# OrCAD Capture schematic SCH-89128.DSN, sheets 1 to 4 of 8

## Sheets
1 08 K20: size D; title: PNEV7220BP2; rev: D; company: NXP Semiconductors; note: SCH-89128 PDF: SPF-89128; note: 6501 William Cannon Drive West; note: Austin, TX 78735-8598
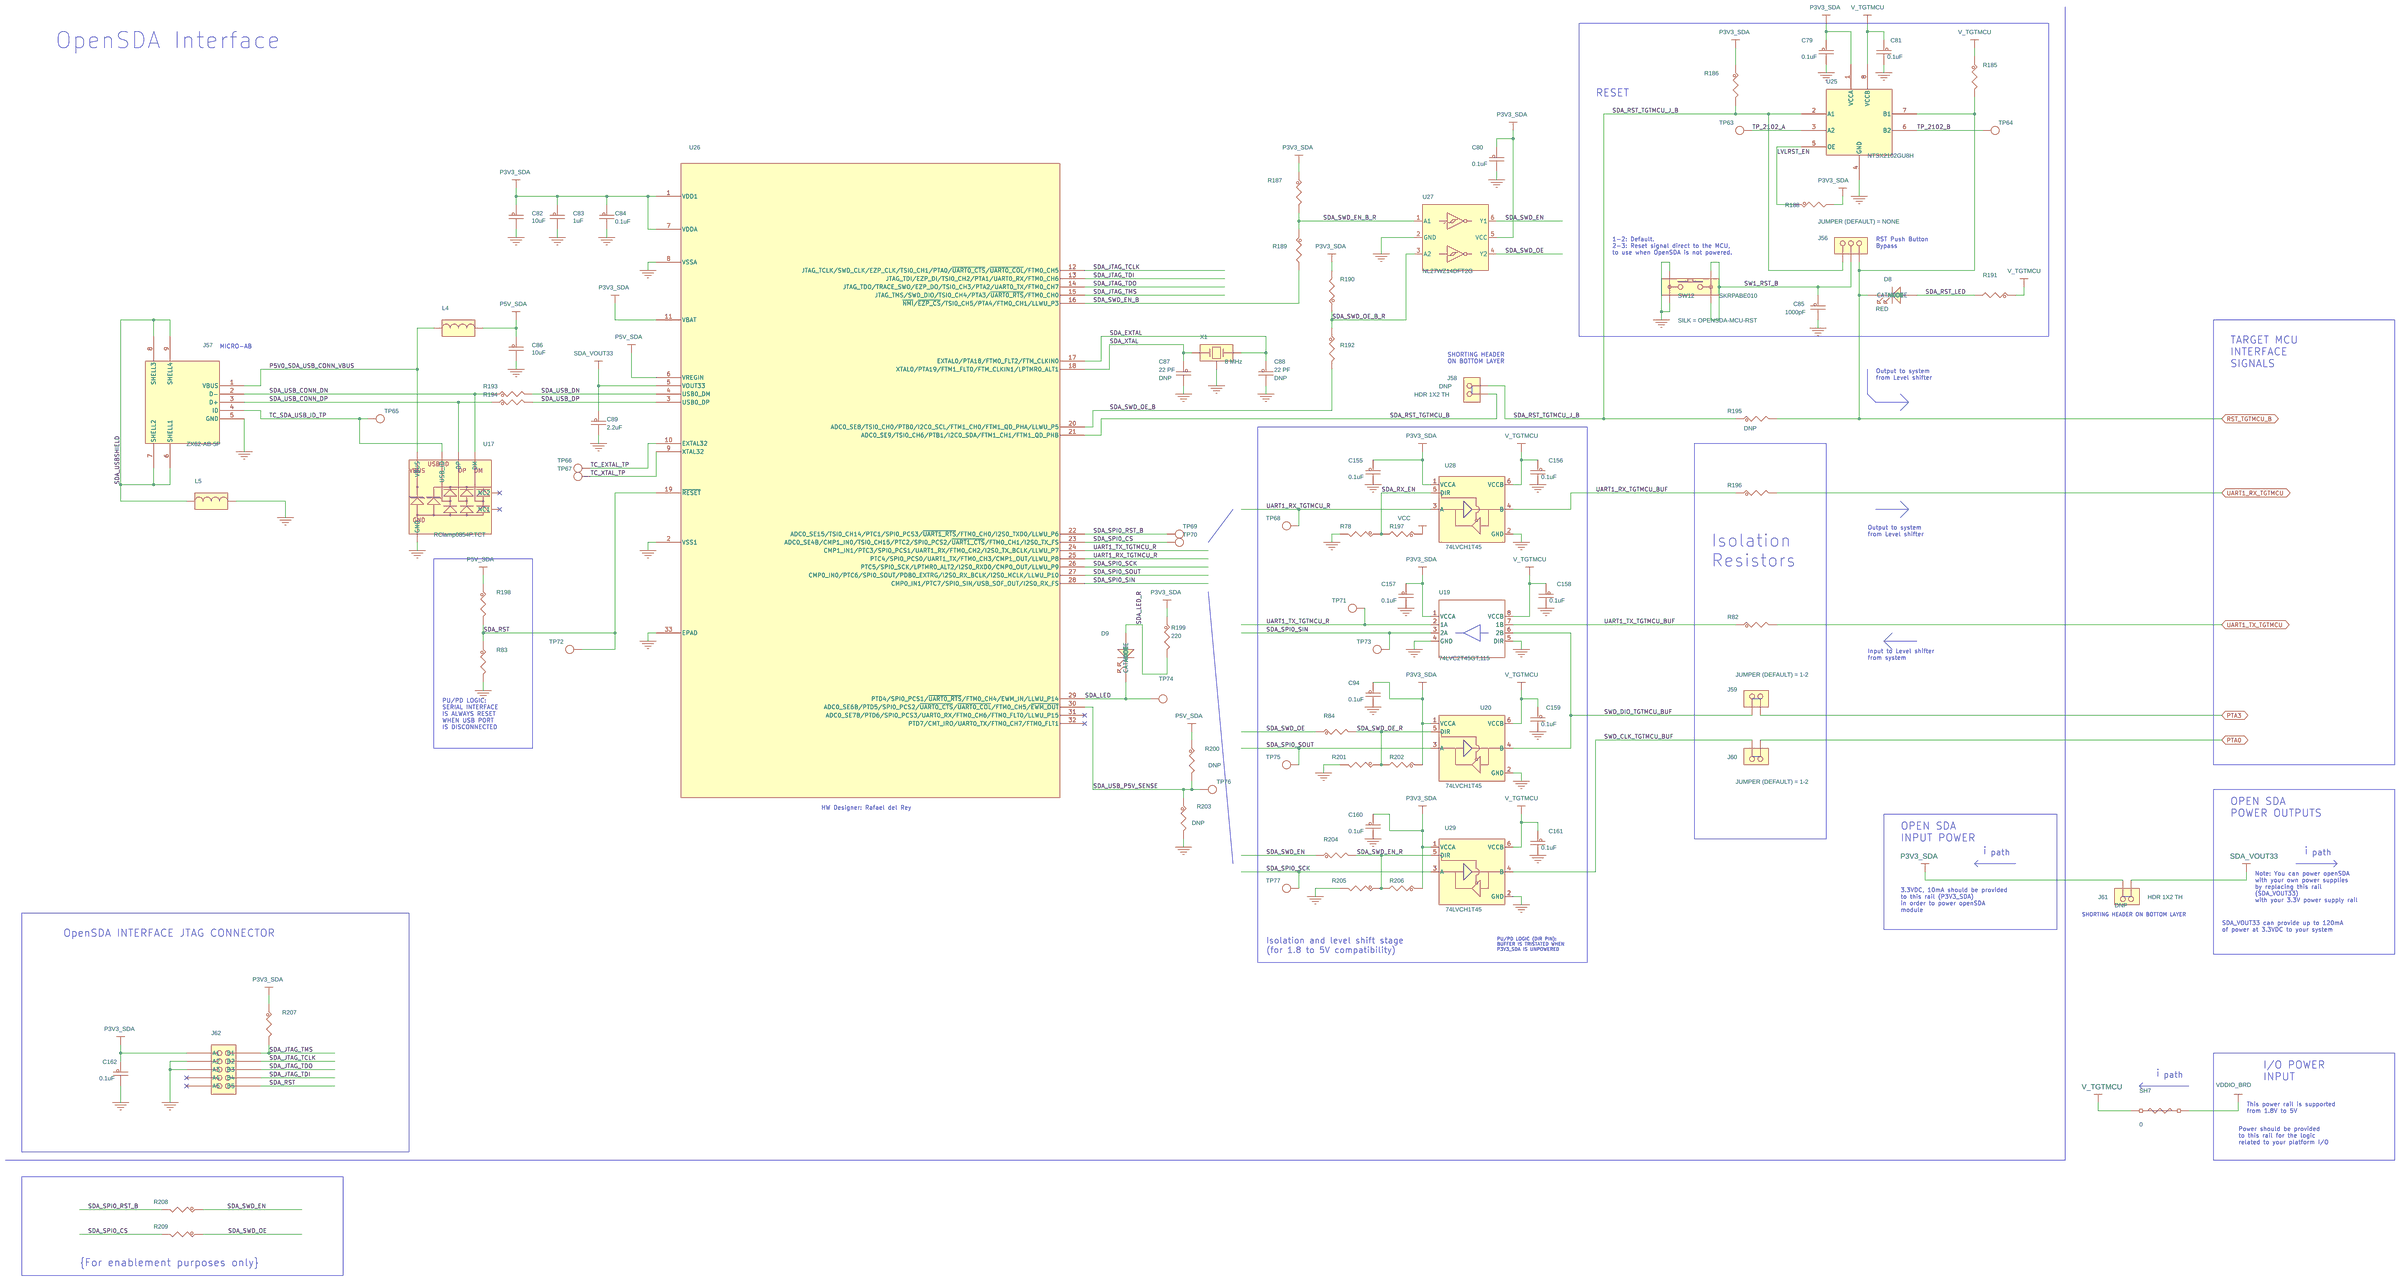
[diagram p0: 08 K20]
2 07 K82: size D
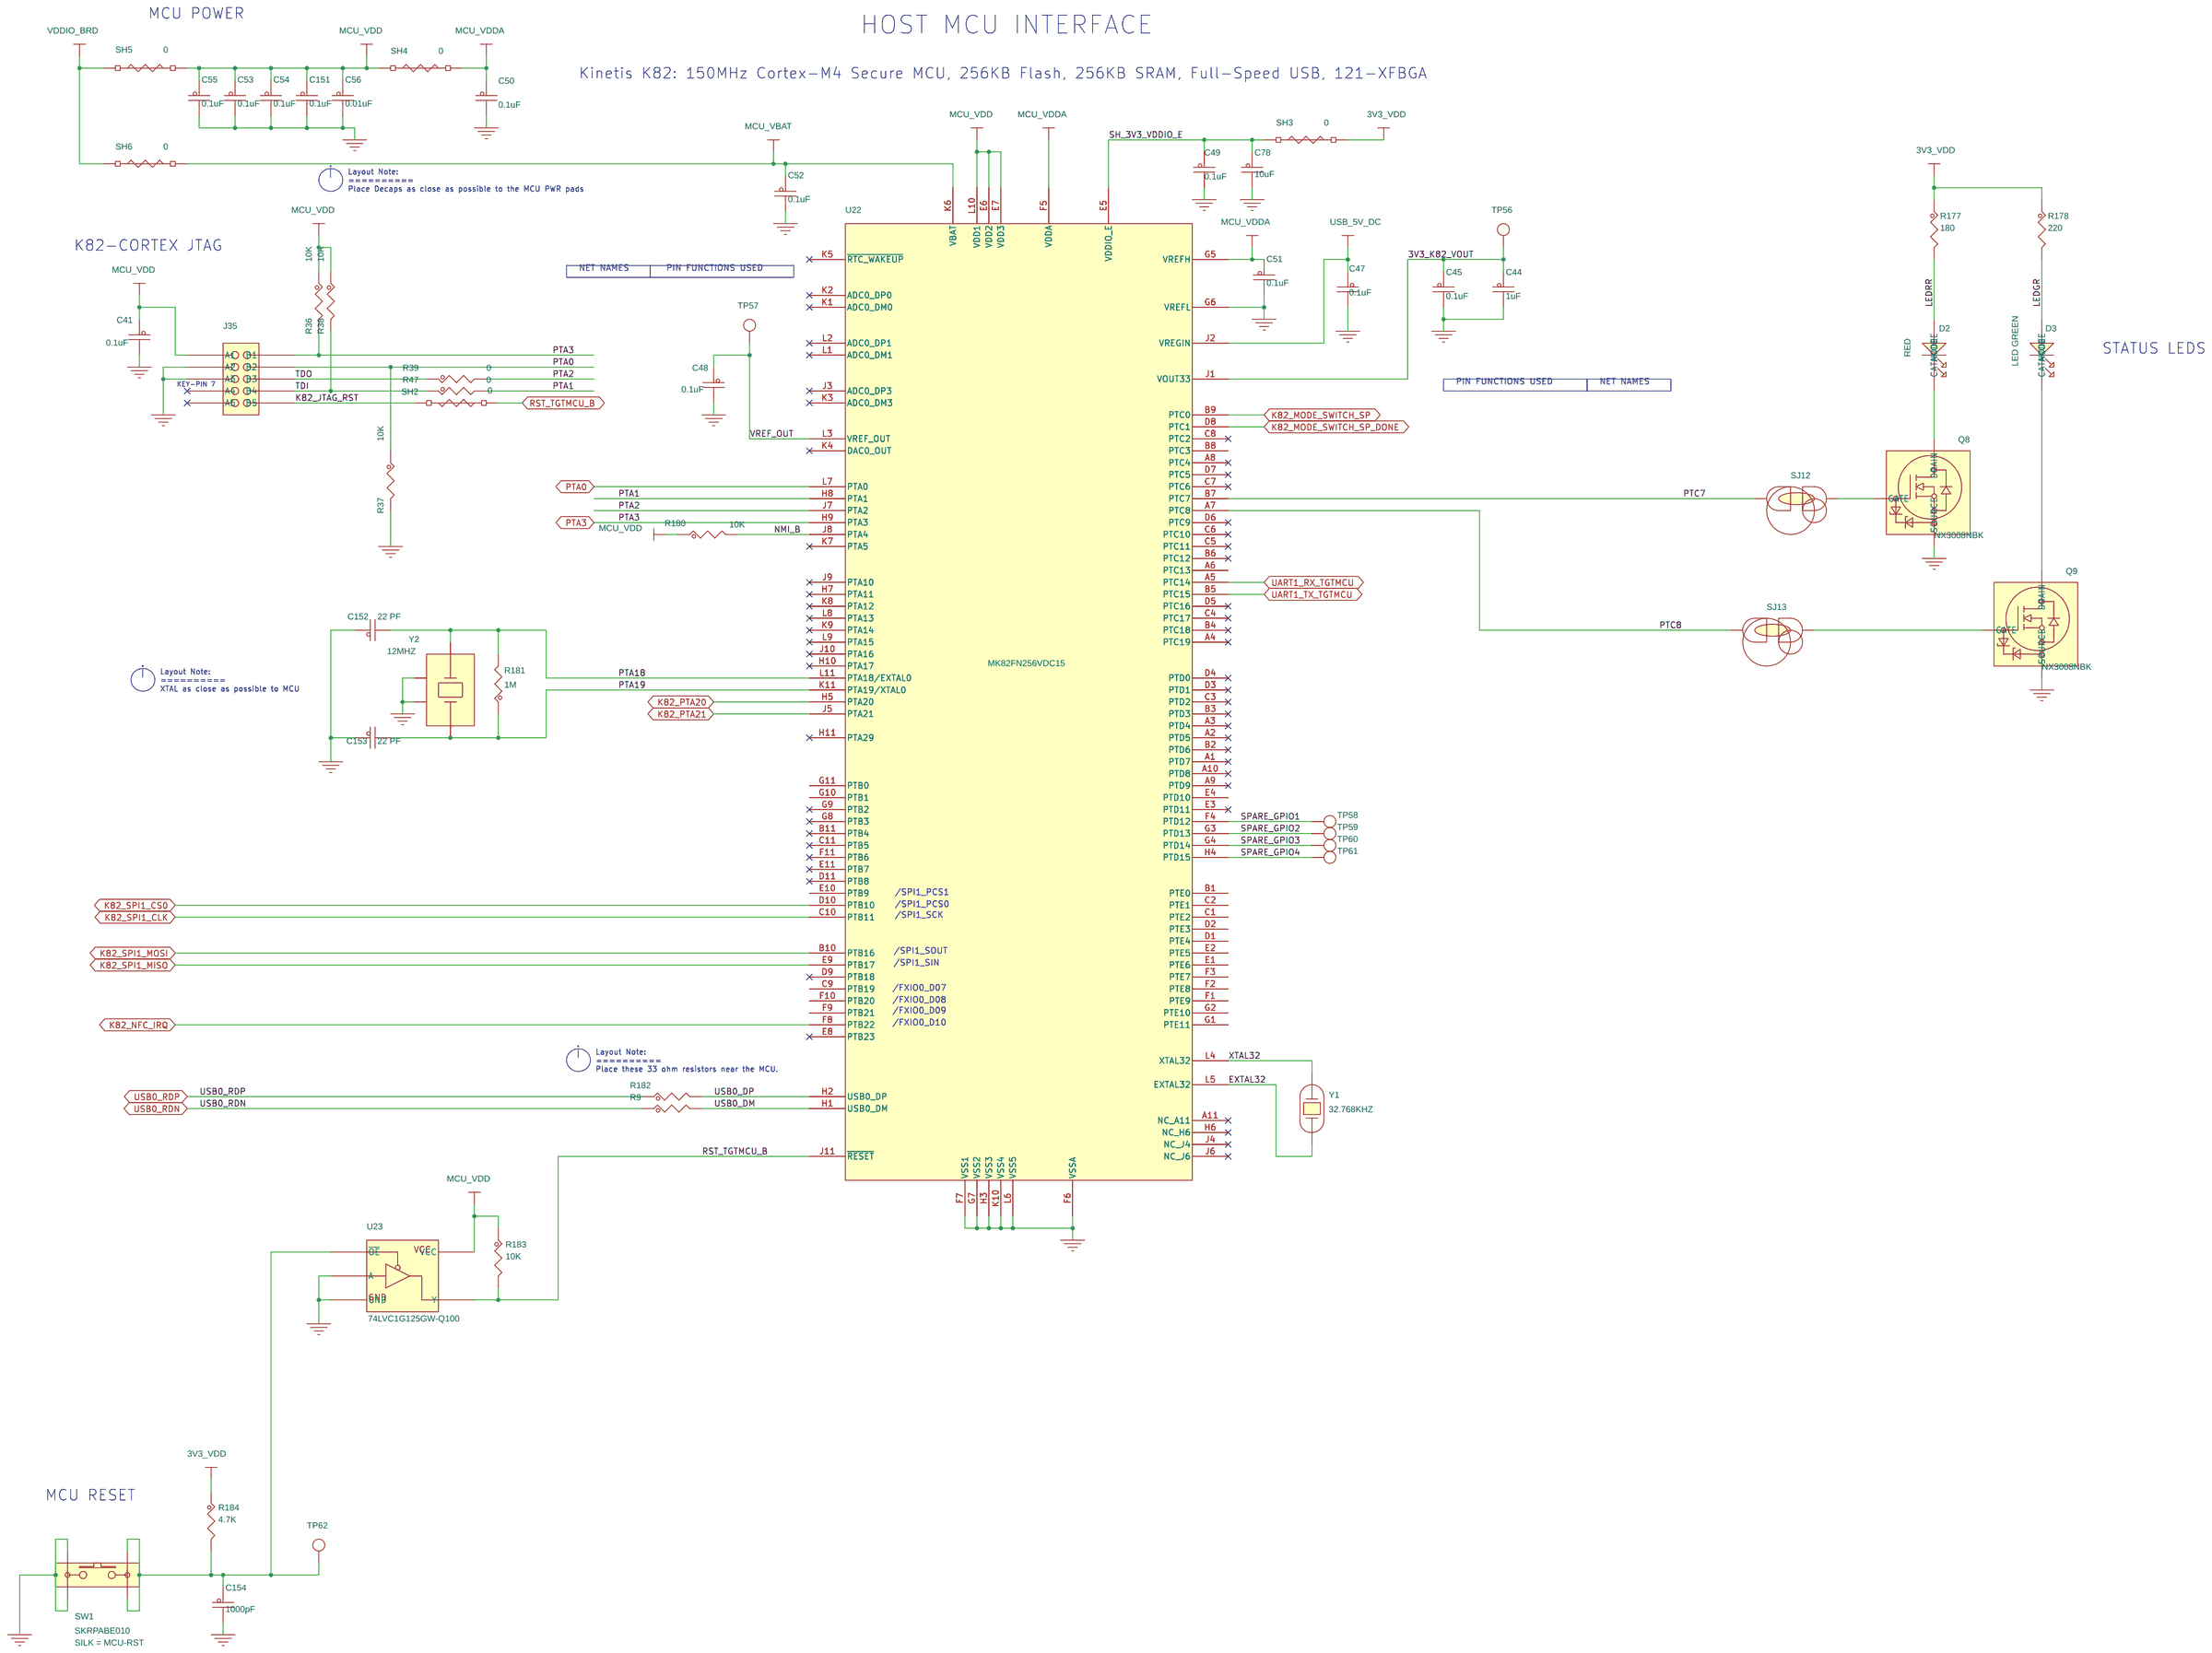
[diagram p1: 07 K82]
3 01 Title
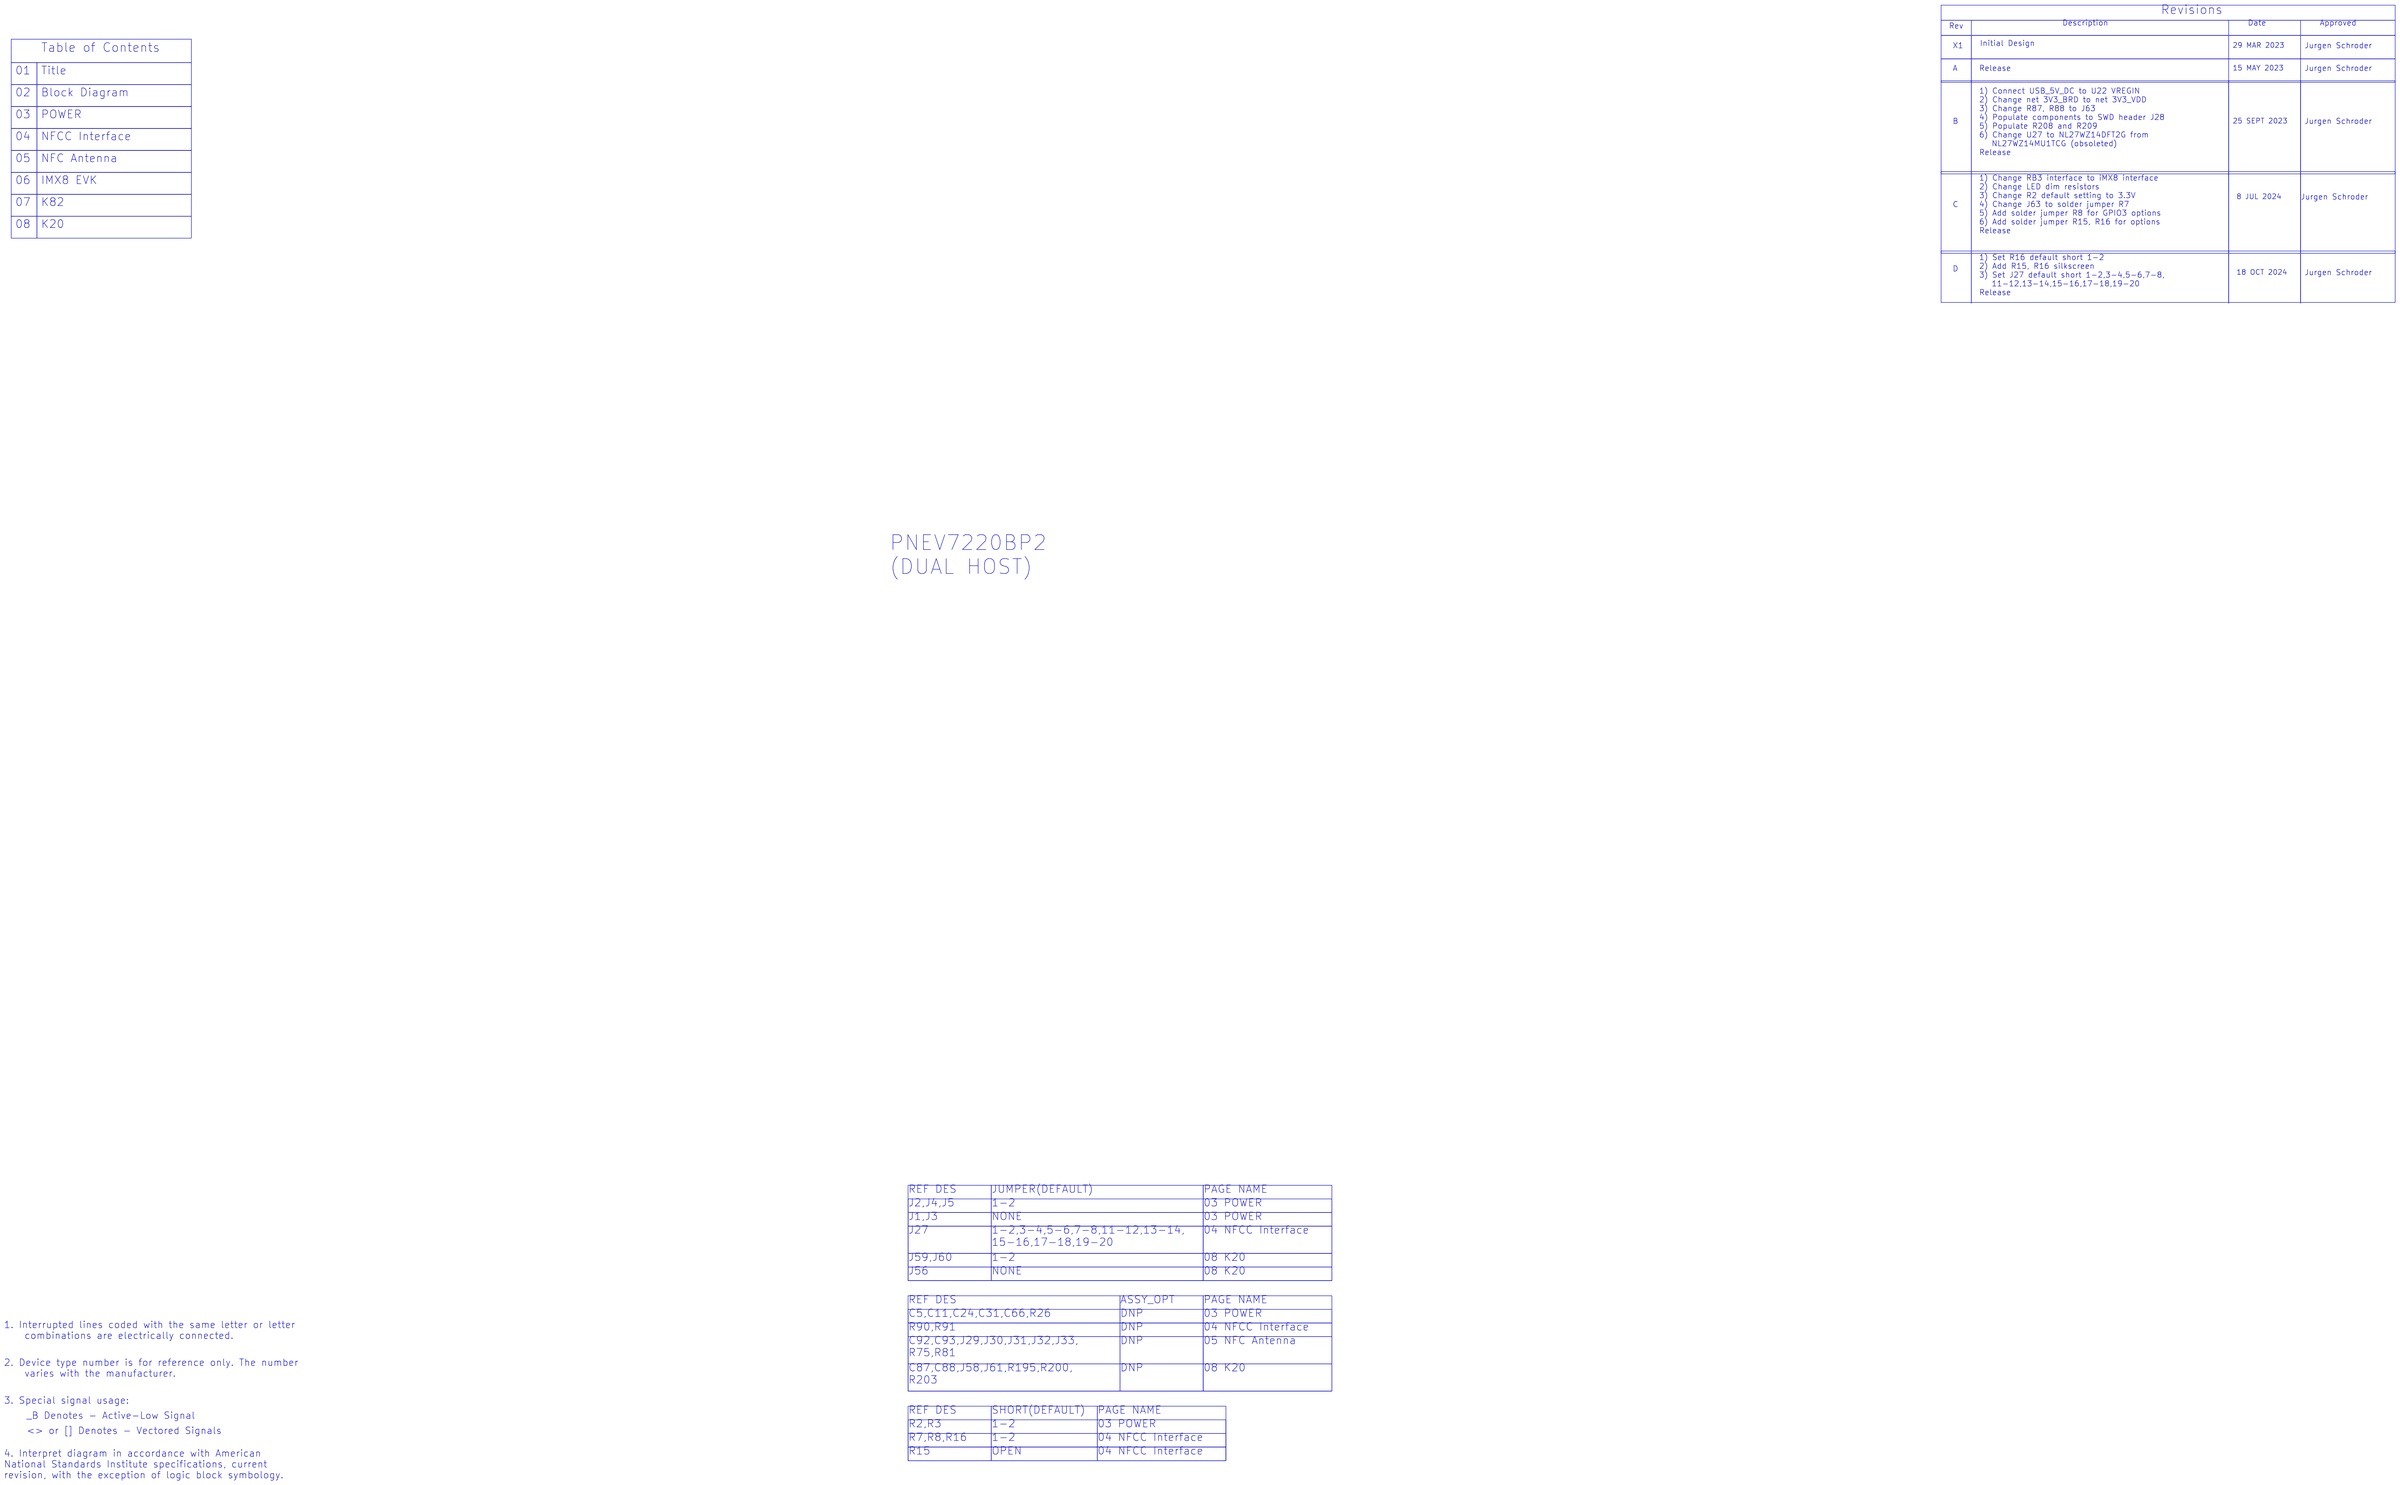
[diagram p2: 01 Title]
4 02 Block Diagram
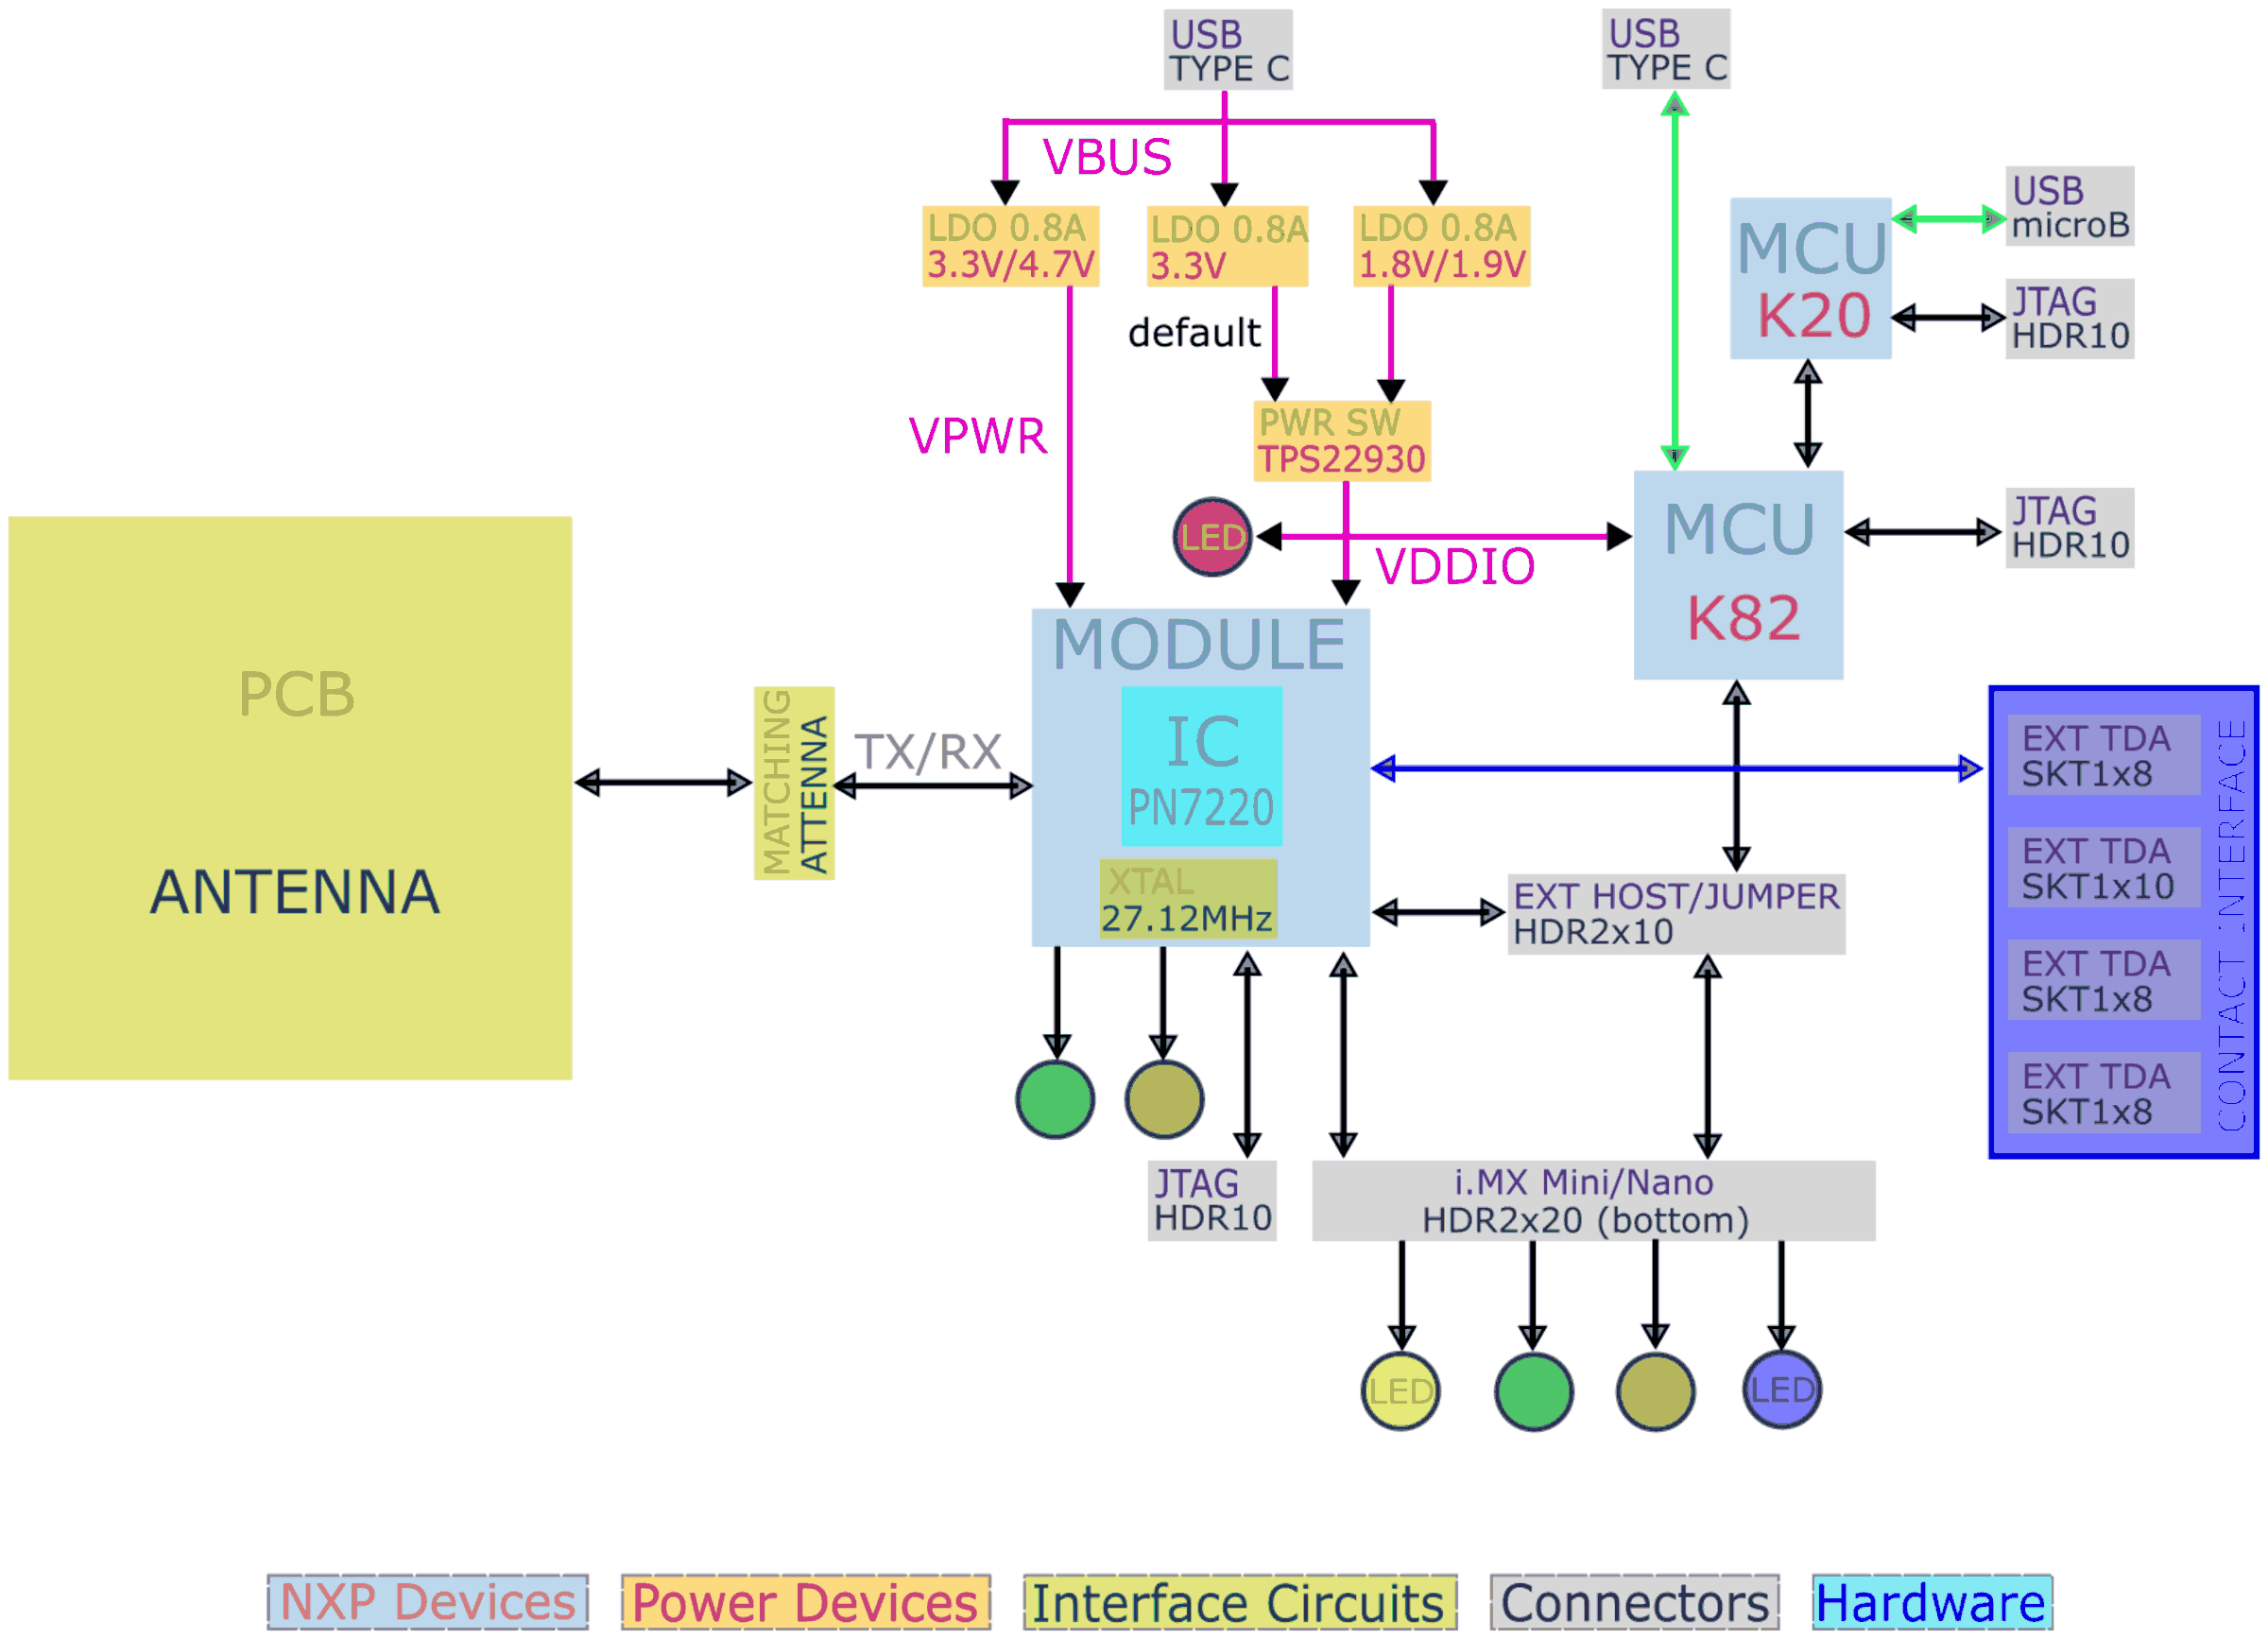
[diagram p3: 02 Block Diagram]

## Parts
sheet 07 K82
C41  0.1uF  [CC0402_25]
C44  1uF  [CC0603_OV]
C45  0.1uF  [CC0402_25]
C47  0.1uF  [CC0402_25]
C48  0.1uF  [CC0402_25]
C49  0.1uF  [CC0402_25]
C50  0.1uF  [CC0402_25]
C51  0.1uF  [CC0402_25]
C52  0.1uF  [CC0402_25]
C53  0.1uF  [CC0402_25]
C54  0.1uF  [CC0402_25]
C55  0.1uF  [CC0402_25]
C56  0.01uF  [CC0402_25]
C78  10uF  [CC0603_OV]
C151  0.1uF  [CC0402_25]
C152  22 PF  [CC0603_OV]
C153  22 PF  [CC0603_OV]
C154  1000pF  [CC0402_25]
D2  RED  [LED_0603]
D3  LED GREEN  [LED_0603]
J35  HDR 2X5  [hdr_5X2_ftsh_th_nsp]
Q8  NX3008NBK  [SOT23_A]
Q9  NX3008NBK  [SOT23_A]
R9  33  [RC0402_25]
R36  10K  [RC0402_25]
R37  10K  [RC0402_25]
R38  10K  [RC0402_25]
R39  0  [RC0603_OV]
R47  0  [RC0603_OV]
R177  180  [RC0402_25]
R178  220  [RC0402_25]
R180  10K  [RC0402_25]
R181  1M  [RC0402_25]
R182  33  [RC0402_25]
R183  10K  [RC0402_25]
R184  4.7K  [RC0402_25]
SH2  0  [SH0603]
SH3  0  [SH0603]
SH4  0  [SH0603]
SH5  0  [SH0603]
SH6  0  [SH0603]
SJ12  0402 JUMPER  [0402_solder_blob_jumper_short]
SJ13  0402 JUMPER  [0402_solder_blob_jumper_short]
SW1  SKRPABE010  [sw4_skrp]
TP56  TPAD_040  [TPAD_040]
TP57  TPAD_040  [TPAD_040]
TP58  TPAD_040  [TPAD_040]
TP59  TPAD_040  [TPAD_040]
TP60  TPAD_040  [TPAD_040]
TP61  TPAD_040  [TPAD_040]
TP62  TPAD_040  [TPAD_040]
U22  MK82FN256VDC15  [BGA121_0P65_8X8MM]
U23  74LVC1G125GW-Q100  [sc70-5]
Y1  32.768KHZ  [XTAL2-3P2X1P5-SM]
Y2  12MHZ  [xtal4_3p3x2p6_sm_fl]
sheet 08 K20
C79  0.1uF  [CC0402_25]
C80  0.1uF  [CC0402_25]
C81  0.1uF  [CC0402_25]
C82  10uF  [CC0603_OV]
C83  1uF  [CC0603_OV]
C84  0.1uF  [CC0402_25]
C85  1000pF  [CC0402_25]
C86  10uF  [CC0603_OV]
C87  22 PF  [CC0603_OV]
C88  22 PF  [CC0603_OV]
C89  2.2uF  [CC0603_OV]
C94  0.1uF  [CC0402_25]
C155  0.1uF  [CC0402_25]
C156  0.1uF  [CC0402_25]
C157  0.1uF  [CC0402_25]
C158  0.1uF  [CC0402_25]
C159  0.1uF  [CC0402_25]
C160  0.1uF  [CC0402_25]
C161  0.1uF  [CC0402_25]
C162  0.1uF  [CC0402_25]
D8  RED  [LED_0603]
D9  LED GREEN  [LED_0603]
J56  HDR TH 1X3  [HDR103]
J57  ZX62-AB-5P  [MICRO_USB_CONN_9PIN]
J58  HDR 1X2 TH  [SH_HDR102_BOTTOM]
J59  HDR 1X2 TH  [HDR_1X2]
J60  HDR 1X2 TH  [HDR_1X2]
J61  HDR 1X2 TH  [SH_HDR102_BOTTOM]
J62  HDR 2X5  [hdr_5X2_ftsh_th_nsp]
L4  330 OHM  [IND_0805]
L5  330 OHM  [IND_0805]
R78  10K  [RC0402_25]
R82  1.0K  [RC0402_25]
R83  10K  [RC0402_25]
R84  0  [RC0603_OV]
R185  180K  [RC0805_OV]
R186  10K  [RC0402_25]
R187  10K  [RC0402_25]
R188  4.7K  [RC0402_25]
R189  0  [RC0603_OV]
R190  10K  [RC0402_25]
R191  100  [RC0402_25]
R192  0  [RC0603_OV]
R193  33  [RC0402_25]
R194  33  [RC0402_25]
R195  0  [RC0603_OV]
R196  1.0K  [RC0402_25]
R197  4.7K  [RC0402_25]
R198  4.7K  [RC0402_25]
R199  220  [RC0402_25]
R200  4.7K  [RC0402_25]
R201  10K  [RC0402_25]
R202  4.7K  [RC0402_25]
R203  10K  [RC0402_25]
R204  0  [RC0603_OV]
R205  10K  [RC0402_25]
R206  4.7K  [RC0402_25]
R207  10K  [RC0402_25]
R208  0  [RC0603_OV]
R209  0  [RC0603_OV]
SH7  0  [SH0603]
SW12  SKRPABE010  [sw4_skrp]
TP63  TPAD_030  [TPAD_030]
TP64  TPAD_030  [TPAD_030]
TP65  TPAD_030  [TPAD_030]
TP66  TPAD_030  [TPAD_030]
TP67  TPAD_030  [TPAD_030]
TP68  TPAD_030  [TPAD_030]
TP69  TPAD_030  [TPAD_030]
TP70  TPAD_030  [TPAD_030]
TP71  TPAD_030  [TPAD_030]
TP72  TPAD_030  [TPAD_030]
TP73  TPAD_030  [TPAD_030]
TP74  TPAD_030  [TPAD_030]
TP75  TPAD_030  [TPAD_030]
TP76  TPAD_030  [TPAD_030]
TP77  TPAD_030  [TPAD_030]
U17  RClamp0854P.TCT  [slp1616p6]
U19  74LVC2T45GT,115  [xson_8p]
U20  74LVCH1T45  [udfn6_1x1p5mm]
U25  NTSX2102GU8H  [xqfn8_1p45x1p25mm]
U26  MK20DX128VFM5  [QFN32_S142EP]
U27  NL27WZ14DFT2G  [sc-88_6p]
U28  74LVCH1T45  [udfn6_1x1p5mm]
U29  74LVCH1T45  [udfn6_1x1p5mm]
X1  8 MHz  [XTAL3_3P35X1P45_SM]

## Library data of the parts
C41 C45 C47 C48 C50-C55 C79-C81 C84 C94 C151 C155-C162 = CAP_NP: CAP CER 0.1UF 16V 10% X5R 0402; AGILE_PN: 150-75663; CAD_APPROVED: Yes; FPLIST: CC0402_25,CC0402_HD,0402_CC,CC0402_18,capc0402_l; HEIGHT: 1; MFG_NAME01: MURATA; MFG_PN01: GRM155R61C104KA88D; Package Size: 1x0.5MM; Package Type: SMT; ROHS: NULL; Rated Voltage: 16V; TOL: 10%; Temp Range: -55C to +85C; Tolerance: 10%; VOLTAGE: 16V
C44 = CAP_NP: CAP CER 1uF 16V 10% X7R 0603; AGILE_PN: 150-79460; CAD_APPROVED: Yes; FPLIST: CC0603_OV,CC0603,0603_CC; HEIGHT: 0.9mm; MFG_NAME01: TDK; MFG_PN01: C1608X7R1C105K080AC; Package Size: 0603; ROHS: NULL; Rated Voltage: 16V; TOL: 10%; Temp Range: -55C to +125C; Tolerance: 10%; VOLTAGE: 16V
C49 = CAP_NP: CAP CER 0.1UF 16V 10% X5R 0402; AGILE_PN: 150-75663; CAD_APPROVED: Yes; FPLIST: CC0402_25,CC0402_HD,0402_CC,CC0402_18,capc0402_l; HEIGHT: 1; MFG_NAME01: MURATA; MFG_PN01: GRM155R61C104KA88D; PRIORITY_PN: 021-00169; Package Size: 1x0.5MM; Package Type: SMT; ROHS: NULL; Rated Voltage: 16V; Temp Range: -55C to +85C; Tolerance: 10%; VOLTAGE: 16V
C56 = CAP_NP: CAP CER 0.01UF 25V 10% X7R 0402; AGILE_PN: 150-75183; CAD_APPROVED: Yes; FPLIST: CC0402_25,CC0402_HD,0402_CC; HEIGHT: 0.635; MFG_NAME01: AVX; MFG_PN01: 04023C103KAT2A; ROHS: Yes; Rated Voltage: 25V; TOL: 20%; Temp Range: -55C to +125C; Tolerance: 10%; VOLTAGE: 25V
C78 = CAP_NP: CAP CER 10.0uF 16V 10% X5R 0603; AGILE_PN: 150-80060; CAD_APPROVED: Yes; FPLIST: CC0603_OV,CC0603,0603_CC,cc0603_0805_nsp; HEIGHT: 0.9; MFG_NAME01: MURATA; MFG_PN01: GRM188R61C106KAALD; Package Size: 0603; Package Type: SMT; ROHS: Yes; Rated Voltage: 16V; TOL: 10%; Temp Range: -55C to +85C; Temp_Range: -55°C to +85°C; Tolerance: 10%; VOLTAGE: 16V
C152 C153 = CAP_NP: CAP CER 22PF 50V 5% C0G 0603; AGILE_PN: 150-75189; CAD_APPROVED: Yes; FPLIST: CC0603_OV,CC0603,0603_CC; HEIGHT: 1.016; MFG_NAME01: WURTH ELEKTRONIK EISOS GMBH & CO. KG (ELECTRONIC & ELECTROMEHANICAL COMP); MFG_PN01: 885012006053; Package Size: 0603; Package Type: Tape & reel; ROHS: Yes; Rated Voltage: 50V; Temp Range: -55C to +125C; Tolerance: 5%; VOLTAGE: 50V
C85 C154 = CAP_NP: CAP CER 1000pF 50V 10% X7R AEC-Q200 0402; AGILE_PN: 150-79040; CAD_APPROVED: Yes; FPLIST: CC0402_25,CC0402_HD,0402_CC; HEIGHT: 0.55; MFG_NAME01: MURATA; MFG_PN01: GCM155R71H102KA37D; Package Size: 0402; Package Type: Paper Tape; ROHS: Yes; Rated Voltage: 50V; Temp Range: -55C to +125C; Tolerance: 10%; VOLTAGE: 50V
D2 D8 = LED: LED ULTRA BRIGHT RED SGL 30MA 0603; AGILE_PN: 370-75079; CAD_APPROVED: Yes; HEIGHT: 0.9; MFG_NAME01: LITE ON; MFG_PN01: LTST-C190KRKT; ROHS: Yes; Rated Voltage: 2V; Temp Range: -30° C to + 85° C; VOLTAGE: 2V
D3 D9 = LED: LED GRN SGL 20MA 0603; AGILE_PN: 370-76565; CAD_APPROVED: Yes; HEIGHT: 0.67; MFG_NAME01: OSRAM; MFG_PN01: LG L29K-G2J1-24-Z; ROHS: Yes; Rated Voltage: 1.7V
J35 J62 = CONN_HDR_5X2: HDR 2X5 TH 50MIL CTR 167H AU 91L; AGILE_PN: 210-80192; CAD_APPROVED: Yes; FPLIST: hdr_5X2_ftsh_th,hdr_5X2_ftsh_th_nsp; HEIGHT: 4.25; MFG_NAME01: ANYTRONIC CORPORATION LIMITED; MFG_PN01: 0922S0205011N6T-2LF; ROHS: NULL
Q8 Q9 = NMOS_NX3008NBK: TRAN NMOS PWR 30V 400mA AEC-Q101 SOT23; AGILE_PN: 480-79305; CAD_APPROVED: Yes; FPLIST: SOT23_A,TO-236; HEIGHT: 1.1; MFG_NAME01: NEXPERIA; MFG_PN01: NX3008NBK,215; ROHS: Yes
R9 R182 = RES: RES MF 33.0 OHM 1/16W 1% 0402; AGILE_PN: 470-75790; CAD_APPROVED: Yes; FPLIST: RC0402_25,RC0402_HD,RC0402_X2,0402_CC; HEIGHT: 0.4; MFG_NAME01: VISHAY; MFG_PN01: CRCW040233R0FKEDC; ROHS: Yes; TOL: 1%; Tolerance: 1%
R36-R38 R180 = RES: RES MF 10K 1/16W 1% 0402; AGILE_PN: 470-80452; CAD_APPROVED: Yes; FPLIST: RC0402_25,RC0402_HD,0402_CC,RC0402_X2; HEIGHT: 0.40; MFG_NAME01: VISHAY; MFG_PN01: CRCW040210K0FKEDC; ROHS: Yes; TOL: 1%; Tolerance: 1%
R39 R47 = RES: RES MF ZERO OHM 1/10W -- 0603; AGILE_PN: 470-80866; CAD_APPROVED: Yes; FPLIST: RC0603_OV,RC0603,R603-X2,0603_CC; HEIGHT: 0.6; MFG_NAME01: VISHAY; MFG_PN01: CRCW06030000Z0EAC; ROHS: NULL; TOL: 1%; Temp Range: –55 °C to +155 °C
R177 = RES: RES MF 180 OHM 1/16W 1% 0402; AGILE_PN: 470-30765; CAD_APPROVED: Yes; FPLIST: RC0402_25,RC0402_HD,0402_CC; HEIGHT: 0.40; MFG_NAME01: WALSIN TECHNOLOGY CORP.; MFG_PN01: WR04X1800FTL; ROHS: Yes; Tolerance: 1%
R178 R199 = RES: RES MF 220 OHM 1/16W 5% 0402; AGILE_PN: 470-75607; CAD_APPROVED: Yes; FPLIST: RC0402_25,RC0402_HD,0402_CC; HEIGHT: 0.45; MFG_NAME01: NIC COMPONENTS CORP; MFG_PN01: NRCL04J221TRF; ROHS: Yes; Tolerance: 5%
R181 = RES: RES MF 1M 1/10W 5% AEC-Q200 0402; AGILE_PN: 470-79978; CAD_APPROVED: Yes; FPLIST: RC0402_25,RC0402_HD,0402_CC; HEIGHT: 0.4; MFG_NAME01: KOA SPEER; MFG_PN01: RK73B1ETTP105J; ROHS: Yes; Temp Range: -55&#8451; to 155&#8451;; Temp_Range: -55&#8451; to 155&#8451;; Tolerance: 5%; VOLTAGE: 50V
R78 R183 R186 R187 R190 R201 R205 = RES: RES MF 10K 1/16W 1% 0402; AGILE_PN: 470-80452; CAD_APPROVED: Yes; FPLIST: RC0402_25,RC0402_HD,0402_CC,RC0402_X2; HEIGHT: 0.40; MFG_NAME01: VISHAY; MFG_PN01: CRCW040210K0FKEDC; ROHS: Yes; TOL: 5%; Tolerance: 1%
R184 = RES: RES MF 4.70K 1/16W 1% 0402; AGILE_PN: 470-75418; CAD_APPROVED: Yes; FPLIST: RC0402_25,RC0402_HD,0402_CC; HEIGHT: 0.4; MFG_NAME01: WALSIN TECHNOLOGY CORP.; MFG_PN01: WR04X4701FTL; ROHS: Yes; TOL: 5%; Tolerance: 1%; VOLTAGE: 1/16W
SH2-SH7 = RES_SHORT-2: ZERO OHM CUT TRACE 0603 PADS; NO PART TO ORDER; AGILE_PN: 470-80018; CAD_APPROVED: Yes; FPLIST: SH0603,SH0603_CC,SH0603-X2_PIN1TO2,SH0603-X2_PIN2TO3; HEIGHT: 0.1; ROHS: NULL
SJ12 SJ13 = 2_Pad_Solder_Blob_Jumper: SOLDER BLOB JUMPER 0402 SHORT NO PART TO ORDER; AGILE_PN: 470-81066; CAD_APPROVED: Yes; HEIGHT: 0.1; MFG_NAME01: NA; MFG_PN01: NO PART TO ORDER1; ROHS: Yes
SW1 = SW_TC_SPST_4P: SW SPST PB SMT 16V 20MA; 3D_Mechanical_Footprint_File: http://fcl.am.freescale.net/ALLEGRO/step/sw4_skrp.step; AGILE_PN: 510-75638; CAD_APPROVED: Yes; HEIGHT: 2.5; MFG_NAME01: ALPS ELECTRIC (USA) INC.; ROHS: Yes; SILK: MCU-RST; VOLTAGE: 16V
TP56-TP62 = TESTLOOP: TEST POINT PAD 40MIL DIA SMT, NO PART TO ORDER; AGILE_PN: 211-76643; CAD_APPROVED: Yes; HEIGHT: 0.1; MFG_NAME01: NOTACOMPONENT; MFG_PN01: NOTACOMPONENT; ROHS: Yes
U22 = MK82FN256VDC_BGA_121P_A: IC MCU 32BIT 256KB FLASH 256KB SRAM 150MHZ 1.71-3.6V XFBGA121; 3D_Mechanical_Footprint_File: http://fcl.am.freescale.net/ALLEGRO/step/bga121_0p65_8x8mm.STEP; AGILE_PN: 344-02273; CAD_APPROVED: Yes; HEIGHT: 0.5; MFG_NAME01: NXP SEMICONDUCTOR; ROHS: Yes; Temp Range: -40C to +105C; Temp_Range: -40C to +105C; VOLTAGE: 1.71-3.6V
U23 = 1G125: IC BUFFER LINE DRIVER 3ST 1.65-5.5V AEC-Q100 TSSOP5; 3D_Mechanical_Footprint_File: http://fcl.am.freescale.net/ALLEGRO/step/sc70-5.STEP; AGILE_PN: 312-81316; CAD_APPROVED: Yes; HEIGHT: 1.1; MFG_NAME01: NEXPERIA; ROHS: Yes; VOLTAGE: 1.65-5.5V
Y1 = XTAL: XTAL 32.768KHZ 12.5PF 20PPM 3.2X1.5MM SMT; 3D_Mechanical_Footprint_File: http://fcl.am.freescale.net/ALLEGRO/step/xtal2-3p2x1p5-sm.step; AGILE_PN: 230-77653; CAD_APPROVED: Yes; HEIGHT: 0.9; MFG_NAME01: ABRACON CORPORATION; MFG_PN01: ABS07-32.768KHZ-T; ROHS: Yes
Y2 = XTAL_13: XTAL 12MHZ 20PF 30PPM -- SMT; 3D_Mechanical_Footprint_File: http://fcl.am.freescale.net/ALLEGRO/step/xtal4_3p3x2p6_sm_fl.STEP; AGILE_PN: 230-77798; CAD_APPROVED: Yes; HEIGHT: 0.75; MFG_NAME01: Diodes Incorporated; MFG_PN01: FL1200050; ROHS: Yes
C82 C86 = CAP_NP: CAP CER 10.0uF 16V 10% X5R 0603; AGILE_PN: 150-80060; CAD_APPROVED: Yes; FPLIST: CC0603_OV,CC0603,0603_CC,cc0603_0805_nsp; HEIGHT: 0.9; MFG_NAME01: MURATA; MFG_PN01: GRM188R61C106KAALD; Package Size: 0603; Package Type: SMT; ROHS: Yes; Rated Voltage: 16V; Temp Range: -55C to +85C; Temp_Range: -55°C to +85°C; Tolerance: 10%; VOLTAGE: 16V
C83 = CAP_NP: CAP CER 1uF 16V 10% X7R 0603; AGILE_PN: 150-79460; CAD_APPROVED: Yes; FPLIST: CC0603_OV,CC0603,0603_CC; HEIGHT: 0.9mm; MFG_NAME01: TDK; MFG_PN01: C1608X7R1C105K080AC; Package Size: 0603; ROHS: NULL; Rated Voltage: 16V; Temp Range: -55C to +125C; Tolerance: 10%; VOLTAGE: 16V
C87 C88 = CAP_NP: CAP CER 22PF 50V 5% C0G 0603; AGILE_PN: 150-75189; ASSY_OPT: DNP; CAD_APPROVED: Yes; FPLIST: CC0603_OV,CC0603,0603_CC; HEIGHT: 1.016; MFG_NAME01: WURTH ELEKTRONIK EISOS GMBH & CO. KG (ELECTRONIC & ELECTROMEHANICAL COMP); MFG_PN01: 885012006053; Package Size: 0603; Package Type: Tape & reel; ROHS: Yes; Rated Voltage: 50V; Temp Range: -55C to +125C; Tolerance: 5%; VOLTAGE: 50V
C89 = CAP_NP: CAP CER 2.2UF 6.3V 10% X5R 0603; AGILE_PN: 150-76330; CAD_APPROVED: Yes; FPLIST: CC0603_OV,CC0603,0603_CC; HEIGHT: 0.9; MFG_NAME01: KEMET; MFG_PN01: C0603C225K9PAC; Package Size: 0603; Package Type: Tape&reel; ROHS: Yes; Rated Voltage: 6.3V; Temp Range: -55C to +85C; Tolerance: 10%; VOLTAGE: 6.3V
J56 = CONN_HDR_3X1: HDR 1X3 TH 100MIL SP 339H AU 100L; 3D_Mechanical_Footprint_File: http://fcl.am.freescale.net/ALLEGRO/step/hdr103.STEP; AGILE_PN: 210-75726; CAD_APPROVED: Yes; HEIGHT: 8.65; JUMPER (DEFAULT): NONE; MFG_NAME01: SAMTEC; MFG_PN01: TSW-103-07-G-S; Package Size: 7.62 x 2.54 mm; ROHS: NULL; Temp Range: -55°C to +125°C; VOLTAGE: 450 - 550 VAC
J57 = MICRO_USB_CONN_9PIN: CON 5 USB2.0 MICRO-AB RA SKT SMT 0.65MM SP AU; 3D_Mechanical_Footprint_File: http://fcl.am.freescale.net/ALLEGRO/step/micro_usb_conn_9pin.step; AGILE_PN: 211-77482; CAD_APPROVED: Yes; HEIGHT: 2.65; MFG_NAME01: HIROSE; MFG_PN01: ZX62-AB-5PA(31); ROHS: Yes
J58 J61 = CONN_HDR_2X1: HDR 1X2 TH 100MIL SP 339H AU 98L; 3D_Mechanical_Footprint_File: http://fcl.am.freescale.net/ALLEGRO/step/hdr102_338h.STEP; AGILE_PN: 210-75439; ASSY_OPT: DNP; CAD_APPROVED: YES; FPLIST: HDR102,SH_HDR102_BOTTOM; HEIGHT: 8.71; MFG_NAME01: SAMTEC; MFG_PN01: TSW-102-07-G-S; ROHS: NULL; Temp Range: -55°C to +125°C
J59 J60 = CONN_HDR_2X1: HDR 1X2 TH 100MIL SP 339H AU 98L; 3D_Mechanical_Footprint_File: http://fcl.am.freescale.net/ALLEGRO/step/hdr102_338h.STEP; AGILE_PN: 210-75439; CAD_APPROVED: YES; HEIGHT: 8.71; JUMPER (DEFAULT): 1-2; MFG_NAME01: SAMTEC; MFG_PN01: TSW-102-07-G-S; ROHS: NULL; Temp Range: -55°C to +125°C
L4 L5 = BEAD: IND FER BEAD 330OHM@100MHZ 2.5A -- SMT; 3D_Mechanical_Footprint_File: http://fcl.am.freescale.net/ALLEGRO/step/ind_0805.STEP; AGILE_PN: 180-30021; CAD_APPROVED: YES; HEIGHT: 1.05; MFG_NAME01: TDK; MFG_PN01: MPZ2012S331AT000; PART_TYPE: FERRITE; ROHS: Yes; Temp Range: -55°C to +125°C; Tolerance: 25%
R82 R196 = RES: RES MF 1.0K 1/16W 1% 0402; AGILE_PN: 470-76037; CAD_APPROVED: Yes; FPLIST: RC0402_25,RC0402_HD,RC0402_X2,0402_CC; HEIGHT: 0.4; MFG_NAME01: YAGEO AMERICA; MFG_PN01: RC0402FR-071KL; ROHS: Yes; TOL: 1%; Tolerance: 1%; VOLTAGE: 1/16W
R83 R207 = RES: RES MF 10K 1/16W 1% 0402; AGILE_PN: 470-80452; CAD_APPROVED: Yes; FPLIST: RC0402_25,RC0402_HD,0402_CC,RC0402_X2; HEIGHT: 0.40; MFG_NAME01: VISHAY; MFG_PN01: CRCW040210K0FKEDC; ROHS: Yes; Tolerance: 1%
R84 R189 R192 R204 R208 R209 = RES: RES MF ZERO OHM 1/10W -- 0603; AGILE_PN: 470-80866; CAD_APPROVED: Yes; FPLIST: RC0603_OV,RC0603,R603-X2,0603_CC,IND_0603HP_NSP,CC0603_OV_NSP; HEIGHT: 0.6; MFG_NAME01: VISHAY; MFG_PN01: CRCW06030000Z0EAC; ROHS: NULL; Temp Range: –55 °C to +155 °C
R185 = RES: RES MF 180K 1/8W 1% 0805; AGILE_PN: 470-75567; CAD_APPROVED: Yes; FPLIST: RC0805_OV,RC0805,0805_CC; HEIGHT: 0.7; MFG_NAME01: BOURNS; MFG_PN01: CR0805-FX-1803ELF; ROHS: Yes; SIGNAL_MODEL: DEFAULT_RESISTOR_180000OHM_2_1; TOL: 1%; Tolerance: 1%
R188 R197 R198 R202 R206 = RES: RES MF 4.70K 1/16W 1% 0402; AGILE_PN: 470-75418; CAD_APPROVED: Yes; FPLIST: RC0402_25,RC0402_HD,0402_CC; HEIGHT: 0.4; MFG_NAME01: WALSIN TECHNOLOGY CORP.; MFG_PN01: WR04X4701FTL; ROHS: Yes; TOL: 1%; Tolerance: 1%; VOLTAGE: 1/16W
R191 = RES: RES MF 100 OHM 1/16W 5% 0402; AGILE_PN: 470-75591; CAD_APPROVED: Yes; FPLIST: RC0402_25,RC0402_HD,RC0402_X2,0402_CC; HEIGHT: 0.45; MFG_NAME01: BOURNS; MFG_PN01: CR0402-JW-101GLF; ROHS: Yes; TOL: 1%; Tolerance: 5%
R193 R194 = RES: RES MF 33.0 OHM 1/16W 1% 0402; AGILE_PN: 470-75790; CAD_APPROVED: Yes; FPLIST: RC0402_25,RC0402_HD,RC0402_X2,0402_CC; HEIGHT: 0.4; MFG_NAME01: VISHAY; MFG_PN01: CRCW040233R0FKEDC; ROHS: Yes; Tolerance: 1%
R195 = RES: RES MF ZERO OHM 1/10W -- 0603; AGILE_PN: 470-80866; ASSY_OPT: DNP; CAD_APPROVED: Yes; FPLIST: RC0603_OV,RC0603,R603-X2,0603_CC,IND_0603HP_NSP,CC0603_OV_NSP; HEIGHT: 0.6; MFG_NAME01: VISHAY; MFG_PN01: CRCW06030000Z0EAC; ROHS: NULL; TOL: 5%; Temp Range: –55 °C to +155 °C
R200 = RES: RES MF 4.70K 1/16W 1% 0402; AGILE_PN: 470-75418; ASSY_OPT: DNP; CAD_APPROVED: Yes; FPLIST: RC0402_25,RC0402_HD,0402_CC; HEIGHT: 0.4; MFG_NAME01: WALSIN TECHNOLOGY CORP.; MFG_PN01: WR04X4701FTL; ROHS: Yes; TOL: 1%; Tolerance: 1%; VOLTAGE: 1/16W
R203 = RES: RES MF 10K 1/16W 1% 0402; AGILE_PN: 470-80452; ASSY_OPT: DNP; CAD_APPROVED: Yes; FPLIST: RC0402_25,RC0402_HD,0402_CC,RC0402_X2; HEIGHT: 0.40; MFG_NAME01: VISHAY; MFG_PN01: CRCW040210K0FKEDC; ROHS: Yes; Tolerance: 1%
SW12 = SW_TC_SPST_4P: SW SPST PB SMT 16V 20MA; 3D_Mechanical_Footprint_File: http://fcl.am.freescale.net/ALLEGRO/step/sw4_skrp.step; AGILE_PN: 510-75638; CAD_APPROVED: Yes; HEIGHT: 2.5; MFG_NAME01: ALPS ELECTRIC (USA) INC.; ROHS: Yes; SILK: OPENSDA-MCU-RST; VOLTAGE: 16V
TP63-TP77 = TESTLOOP: TEST POINT PAD 30MIL DIA SMT, NO PART TO ORDER; 3D_Mechanical_Footprint_File: http://fcl.am.freescale.net/ALLEGRO/step/tpad_030.STEP; AGILE_PN: 211-76642; CAD_APPROVED: Yes; HEIGHT: 0.1; MFG_NAME01: NOTACOMPONENT; MFG_PN01: NOTACOMPONENT; ROHS: Yes
U17 = RCLAMP1654P_NEW: DIODE TVS ARRAY 3 5.5V SLP1616P6; 3D_Mechanical_Footprint_File: http://fcl.am.freescale.net/ALLEGRO/step/slp1616p6.step; AGILE_PN: 480-78843; CAD_APPROVED: Yes; HEIGHT: 0.65; MFG_NAME01: SEMTECH CORP; ROHS: Yes; Rated Voltage: 5.5V; VOLTAGE: 5.5V
U19 = 74LVC2T45DC_8P: IC XCVR DUAL SUPPLY 1.2-5.5V XSON8; 3D_Mechanical_Footprint_File: http://fcl.am.freescale.net/ALLEGRO/step/xson_8p.step; AGILE_PN: 312-83447; CAD_APPROVED: Yes; HEIGHT: 0.5; MFG_NAME01: Nexperia; Package Size: 1.95 x 1.00; ROHS: Yes; Supply Voltage: 1.2-5.5V; Temp Range: -40°C to +125°C; VOLTAGE: 1.2-5.5V
U20 U28 U29 = 74LVCH1T45_6P: IC XCVR 1BIT 3-STATE DUAL 1.2-5.5V XSON6; AGILE_PN: 312-80758; CAD_APPROVED: Yes; HEIGHT: 0.5; MFG_NAME01: NEXPERIA; MFG_PN01: 74LVCH1T45GM,132; ROHS: Yes; VOLTAGE: 1.2-5.5V
U25 = NTSX2102GD: IC DUAL SUPPLY XCVR 50 MBPS 5.5V XQFN8; 3D_Mechanical_Footprint_File: http://fcl.am.freescale.net/ALLEGRO/step/xqfn8_1p45x1p25mm.STEP; AGILE_PN: 312-80763; CAD_APPROVED: Yes; HEIGHT: 0.5; MFG_NAME01: NXP SEMICONDUCTORS; ROHS: Yes; VOLTAGE: 5.5V
U26 = PK20DX128V_QFN_32P: IC MCU FLASH 128KB 50MHZ 1.71-3.6V QFN32; AGILE_PN: 344-01231; CAD_APPROVED: Yes; HEIGHT: 1; MFG_NAME01: FREESCALE SEMICONDUCTOR; ROHS: Yes; VOLTAGE: 1.71-3.6V
U27 = NL27WZ14: IC INV DUAL SCHMITT TRIGGER 1.65-5.5V SC88; 3D_Mechanical_Footprint_File: http://fcl.am.freescale.net/ALLEGRO/step/sc-88_6p.STEP; AGILE_PN: 312-83970; CAD_APPROVED: Yes; HEIGHT: 1.1; MFG_NAME01: onsemi; Package Size: 6-TSSOP, SC-88, SOT-363; ROHS: Yes; Supply Voltage: 1.65V ~ 5.5V; Temp Range: -55 to +125°C
X1 = XTAL_CS: XTAL 8.00MHZ RSN CERAMIC -- SMT; 3D_Mechanical_Footprint_File: http://fcl.am.freescale.net/ALLEGRO/step/xtal3_3p35x1p45_sm.STEP; AGILE_PN: 230-78262; CAD_APPROVED: Yes; HEIGHT: 0.8; MFG_NAME01: MURATA; MFG_PN01: CSTNE8M00G550000R0; ROHS: Yes; Temp Range: -40 to +85°C; Temp_Range: -40 to +85°C

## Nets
3V3_K82_VOUT: C44.1 C45.1 TP56.1(Pin1) U22.J1(VOUT33)
3V3_VDD: R177.1 R178.1 R184.1 SH3.2 ; also on sheet 5 6 8
GND: C41.2 C44.2 C45.2 C47.2 C48.2 C49.2 C50.2 C51.2 C52.2 C53.2 C54.2 C55.2 C56.2 C78.2 C79.2 C80.2 C81.2 C82.2 C83.2 C84.2 C85.2 C86.2 C87.2 C88.2 C89.2 C94.2 C151.2 C152.1 C153.1 C154.2 C155.2 C156.2 C157.2 C158.2 C159.2 C160.2 C161.2 C162.2 J35.3(A2) J35.5(A3) J57.5(GND) J62.3(A2) J62.5(A3) L5.2 Q8.2(SOURCE) Q9.2(SOURCE) R37.2 R78.2 R83.2 R201.2 R203.2 R205.2 SW1.1 SW1.2 SW12.1 SW12.2 U17.7(GND) U19.4(GND) U19.5(DIR) U20.2(GND) U22.F6(VSSA) U22.F7(VSS1) U22.G6(VREFL) U22.G7(VSS2) U22.H3(VSS3) U22.K10(VSS4) U22.L6(VSS5) U23.2(A) U23.3(GND) U25.4(GND) U26.2(VSS1) U26.8(VSSA) U26.33(EPAD) U27.2(GND) U28.2(GND) U29.2(GND) X1.2 Y2.2 Y2.4 ; also on sheet 5 6 7 8
P3V3_SDA: C79.1 C80.1 C82.1 C83.1 C84.1 C94.1 C155.1 C157.1 C160.1 C162.1 J61.1 J62.1(A1) R186.1 R187.1 R188.2 R190.2 R197.1 R199.1 R202.1 R206.1 R207.1 U19.1(VCCA) U20.1(VCCA) U25.1(VCCA) U26.1(VDD1) U26.7(VDDA) U26.11(VBAT) U27.5(VCC) U28.1(VCCA) U29.1(VCCA)
P5V0_SDA_USB_CONN_VBUS: J57.1(VBUS) L4.1 U17.6(VBUS)
P5V_SDA: C86.1 L4.2 R198.1 R200.1 U26.6(VREGIN)
VDDIO_BRD: SH5.1 SH6.1 SH7.2 ; also on sheet 5 6
EXTAL32: U22.L5(EXTAL32) Y1.1
K82_JTAG_RST: J35.10(B5) SH2.2
K82_MODE_SWITCH_SP: U22.B9(PTC0) ; also on sheet 6
K82_MODE_SWITCH_SP_DONE: U22.D8(PTC1) ; also on sheet 6
K82_NFC_IRQ: U22.F8(PTB22) ; also on sheet 6
K82_PTA20: U22.H5(PTA20) ; also on sheet 6
K82_PTA21: U22.J5(PTA21) ; also on sheet 6
K82_SPI1_CLK: U22.C10(PTB11) ; also on sheet 6
K82_SPI1_CS0: U22.D10(PTB10) ; also on sheet 6
K82_SPI1_MISO: U22.E9(PTB17) ; also on sheet 6
K82_SPI1_MOSI: U22.B10(PTB16) ; also on sheet 6
LEDGR: D3.A(ANODE) R178.2
LEDRR: D2.A(ANODE) R177.2
LVLRST_EN: R188.1 U25.5(OE)
MCU_VBAT: C52.1 SH6.2 U22.K6(VBAT)
MCU_VDD: C41.1 C53.1 C54.1 C55.1 C56.1 C151.1 J35.1(A1) R36.1 R38.1 R180.1 R183.1 SH4.1 SH5.2 U22.E6(VDD2) U22.E7(VDD3) U22.L10(VDD1) U23.5(VCC)
MCU_VDDA: C50.1 C51.1 SH4.2 U22.F5(VDDA) U22.G5(VREFH)
NMI_B: R180.2 U22.J8(PTA4)
PTA0: J35.4(B2) J60.1 R37.1 U22.L7(PTA0)
PTA1: R47.2 U22.H8(PTA1)
PTA2: R39.2 U22.J7(PTA2)
PTA3: J35.2(B1) J59.1 R36.2 U22.H9(PTA3)
PTA18: C152.2 R181.2 U22.L11(PTA18/EXTAL0) Y2.3
PTA19: C153.2 R181.1 U22.K11(PTA19/XTAL0) Y2.1
PTC7: SJ12.1 U22.B7(PTC7)
PTC8: SJ13.1 U22.A7(PTC8)
RST_TGTMCU_B: D8.C(CATHODE) J56.3 R183.2 R185.2 R195.2 SH2.1 U22.J11(~{RESET}) U23.4(Y) U25.7(B1)
SDA_EXTAL: C88.1 U26.17(EXTAL0/PTA18/FTM0_FLT2/FTM_CLKIN0) X1.3
SDA_JTAG_TCLK: J62.4(B2) U26.12(JTAG_TCLK/SWD_CLK/EZP_CLK/TSI0_CH1/PTA0/~{UART0_CTS}/~{UART0_COL}/FTM0_CH5)
SDA_JTAG_TDI: J62.8(B4) U26.13(JTAG_TDI/EZP_DI/TSI0_CH2/PTA1/UART0_RX/FTM0_CH6)
SDA_JTAG_TDO: J62.6(B3) U26.14(JTAG_TDO/TRACE_SWO/EZP_DO/TSI0_CH3/PTA2/UART0_TX/FTM0_CH7)
SDA_JTAG_TMS: J62.2(B1) R207.2 U26.15(JTAG_TMS/SWD_DIO/TSI0_CH4/PTA3/~{UART0_RTS}/FTM0_CH0)
SDA_LED: D9.C(CATHODE) TP74.1(Pin1) U26.29(PTD4/SPI0_PCS1/~{UART0_RTS}/FTM0_CH4/EWM_IN/LLWU_P14)
SDA_LED_R: D9.A(ANODE) R199.2
SDA_RST: J62.10(B5) R83.1 R198.2 TP72.1(Pin1) U26.19(~{RESET})
SDA_RST_LED: D8.A(ANODE) R191.2
SDA_RST_TGTMCU_B: J58.2 U26.21(ADC0_SE9/TSI0_CH6/PTB1/I2C0_SDA/FTM1_CH1/FTM1_QD_PHB)
SDA_RST_TGTMCU_J_B: J56.1 J58.1 R186.2 R195.1 U25.2(A1)
SDA_RX_EN: R78.1 R197.2 U28.5(DIR)
SDA_SPI0_CS: R209.2 TP70.1(Pin1) U26.23(ADC0_SE4B/CMP1_IN0/TSI0_CH15/PTC2/SPI0_PCS2/~{UART1_CTS}/FTM0_CH1/I2S0_TX_FS)
SDA_SPI0_RST_B: R208.2 TP69.1(Pin1) U26.22(ADC0_SE15/TSI0_CH14/PTC1/SPI0_PCS3/~{UART1_RTS}/FTM0_CH0/I2S0_TXD0/LLWU_P6)
SDA_SPI0_SCK: TP77.1(Pin1) U26.26(PTC5/SPI0_SCK/LPTMR0_ALT2/I2S0_RXD0/CMP0_OUT/LLWU_P9) U29.3(A)
SDA_SPI0_SIN: TP73.1(Pin1) U19.3(2A) U26.28(CMP0_IN1/PTC7/SPI0_SIN/USB_SOF_OUT/I2S0_RX_FS)
SDA_SPI0_SOUT: TP75.1(Pin1) U20.3(A) U26.27(CMP0_IN0/PTC6/SPI0_SOUT/PDB0_EXTRG/I2S0_RX_BCLK/I2S0_MCLK/LLWU_P10)
SDA_SWD_EN: R204.1 R208.1 U27.6(Y1)
SDA_SWD_EN_B: R189.2 U26.16(~{NMI}/~{EZP_CS}/TSI0_CH5/PTA4/FTM0_CH1/LLWU_P3)
SDA_SWD_EN_B_R: R187.2 R189.1 U27.1(A1)
SDA_SWD_EN_R: R204.2 R205.1 R206.2 U29.5(DIR)
SDA_SWD_OE: R84.1 R209.1 U27.4(Y2)
SDA_SWD_OE_B: R192.2 U26.20(ADC0_SE8/TSI0_CH0/PTB0/I2C0_SCL/FTM1_CH0/FTM1_QD_PHA/LLWU_P5)
SDA_SWD_OE_B_R: R190.1 R192.1 U27.3(A2)
SDA_SWD_OE_R: R84.2 R201.1 R202.2 U20.5(DIR)
SDA_USB_CONN_DN: J57.2(D-) R193.1 U17.1(DM)
SDA_USB_CONN_DP: J57.3(D+) R194.1 U17.2(DP)
SDA_USB_DN: R193.2 U26.4(USB0_DM)
SDA_USB_DP: R194.2 U26.3(USB0_DP)
SDA_USB_P5V_SENSE: R200.2 R203.1 TP76.1(Pin1) U26.30(ADC0_SE6B/PTD5/SPI0_PCS2/~{UART0_CTS}/~{UART0_COL}/FTM0_CH5/~{EWM_OUT})
SDA_USBSHIELD: J57.6(SHELL1) J57.7(SHELL2) J57.8(SHELL3) J57.9(SHELL4) L5.1
SDA_VOUT33: C89.1 J61.2 U26.5(VOUT33)
SDA_XTAL: C87.1 U26.18(XTAL0/PTA19/FTM1_FLT0/FTM_CLKIN1/LPTMR0_ALT1) X1.1
SH_3V3_VDDIO_E: C49.1 C78.1 SH3.1 U22.E5(VDDIO_E)
SPARE_GPIO1: TP58.1(Pin1) U22.F4(PTD12)
SPARE_GPIO2: TP59.1(Pin1) U22.G3(PTD13)
SPARE_GPIO3: TP60.1(Pin1) U22.G4(PTD14)
SPARE_GPIO4: TP61.1(Pin1) U22.H4(PTD15)
SW1_RST_B: C85.1 J56.2 SW12.3 SW12.4
SWD_CLK_TGTMCU_BUF: J60.2 U29.4(B)
SWD_DIO_TGTMCU_BUF: J59.2 U19.6(2B) U20.4(B)
TC_EXTAL_TP: TP66.1(Pin1) U26.10(EXTAL32)
TC_SDA_USB_ID_TP: J57.4(ID) TP65.1(Pin1) U17.3(USB_ID)
TC_XTAL_TP: TP67.1(Pin1) U26.9(XTAL32)
TDI: J35.8(B4) R38.2 R47.1
TDO: J35.6(B3) R39.1
TP_2102_A: TP63.1(Pin1) U25.3(A2)
TP_2102_B: TP64.1(Pin1) U25.6(B2)
UART1_RX_TGTMCU: R196.2 U22.A5(PTC14)
UART1_RX_TGTMCU_BUF: R196.1 U28.4(B)
UART1_RX_TGTMCU_R: TP68.1(Pin1) U26.25(PTC4/SPI0_PCS0/UART1_TX/FTM0_CH3/CMP1_OUT/LLWU_P8) U28.3(A)
UART1_TX_TGTMCU: R82.2 U22.B5(PTC15)
UART1_TX_TGTMCU_BUF: R82.1 U19.7(1B)
UART1_TX_TGTMCU_R: TP71.1(Pin1) U19.2(1A) U26.24(CMP1_IN1/PTC3/SPI0_PCS1/UART1_RX/FTM0_CH2/I2S0_TX_BCLK/LLWU_P7)
USB0_DM: R9.2 U22.H1(USB0_DM)
USB0_DP: R182.2 U22.H2(USB0_DP)
USB0_RDN: R9.1 ; also on sheet 5
USB0_RDP: R182.1 ; also on sheet 5
USB_5V_DC: C47.1 U22.J2(VREGIN) ; also on sheet 5
V_TGTMCU: C81.1 C156.1 C158.1 C159.1 C161.1 R185.1 R191.1 SH7.1 U19.8(VCCB) U20.6(VCCB) U25.8(VCCB) U28.6(VCCB) U29.6(VCCB)
VREF_OUT: C48.1 TP57.1(Pin1) U22.L3(VREF_OUT)
XTAL32: U22.L4(XTAL32) Y1.2
N28495927: D3.C(CATHODE) Q9.3(DRAIN)
N28496386: C154.1 R184.2 SW1.3 SW1.4 TP62.1(Pin1) U23.1(~{OE})
N28538592: Q8.1(GATE) SJ12.2
N28538615: Q9.1(GATE) SJ13.2
N28539455: D2.C(CATHODE) Q8.3(DRAIN)

Not connected (* = marked no-connect by the designer): J35 7(A4)* 9(A5)*; J62 7(A4)* 9(A5)*; U17 4(NC1)* 5(NC2)*; U22 A1(PTD7)* A2(PTD5)* A3(PTD4)* A4(PTC19)* A6(PTC13) A8(PTC4)* A9(PTD9)* A10(PTD8)* A11(NC)* B1(PTE0) B2(PTD6)* B3(PTD3)* B4(PTC18)* B6(PTC12)* B8(PTC3) B11(PTB4)* C1(PTE2) C2(PTE1) C3(PTD2)* C4(PTC17)* C5(PTC11)* C6(PTC10)* C7(PTC6)* C8(PTC2)* C9(PTB19) C11(PTB5)* D1(PTE4) D2(PTE3) D3(PTD1)* D4(PTD0)* D5(PTC16)* D6(PTC9)* D7(PTC5)* D9(PTB18)* D11(PTB8)* E1(PTE6) E2(PTE5) E3(PTD11)* E4(PTD10) E8(PTB23)* E10(PTB9) E11(PTB7)* F1(PTE9) F2(PTE8) F3(PTE7) F9(PTB21) F10(PTB20) F11(PTB6)* G1(PTE11) G2(PTE10) G8(PTB3)* G9(PTB2)* G10(PTB1) G11(PTB0) H6(NC)* H7(PTA11)* H10(PTA17)* H11(PTA29)* J3(ADC0_DP3)* J4(NC)* J6(NC)* J9(PTA10)* J10(PTA16)* K1(ADC0_DM0)* K2(ADC0_DP0)* K3(ADC0_DM3)* K4(DAC0_OUT)* K5(~{RTC_WAKEUP})* K7(PTA5)* K8(PTA12)* K9(PTA14)* L1(ADC0_DM1)* L2(ADC0_DP1)* L8(PTA13)* L9(PTA15)*; U26 31(ADC0_SE7B/PTD6/SPI0_PCS3/UART0_RX/FTM0_CH6/FTM0_FLT0/LLWU_P15)* 32(PTD7/CMT_IRO/UART0_TX/FTM0_CH7/FTM0_FLT1)*

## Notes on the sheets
sheet 1
- OpenSDA Interface
- RESET
- 1-2: Default.
  2-3: Reset signal direct to the MCU,
  to use when OpenSDA is not powered.
- RST Push Button
  Bypass
- TARGET MCU
  INTERFACE
  SIGNALS
- MICRO-AB
- SHORTING HEADER
  ON BOTTOM LAYER
- Output to system
  from Level shifter
- Output to system
  from Level shifter
- Isolation
  Resistors
- Input to Level shifter
  from system
- PU/PD LOGIC:
  SERIAL INTERFACE
  IS ALWAYS RESET
  WHEN USB PORT
  IS DISCONNECTED
- OPEN SDA
  POWER OUTPUTS
- HW Designer: Rafael del Rey
- OPEN SDA
  INPUT POWER
- i
- path
- i
- path
- Note: You can power openSDA
  with your own power supplies
  by replacing this rail
  (SDA_VOUT33)
  with your 3.3V power supply rail
- 3.3VDC, 10mA should be provided
  to this rail (P3V3_SDA)
  in order to power openSDA
  module
- SHORTING HEADER ON BOTTOM LAYER
- OpenSDA INTERFACE JTAG CONNECTOR
- SDA_VOUT33 can provide up to 120mA
  of power at 3.3VDC to your system
- Isolation and level shift stage
  (for 1.8 to 5V compatibility)
- PU/PD LOGIC (DIR PIN):
  BUFFER IS TRISTATED WHEN
  P3V3_SDA IS UNPOWERED
- I/O POWER
  INPUT
- i
- path
- This power rail is supported
  from 1.8V to 5V
- Power should be provided
  to this rail for the logic
  related to your platform I/O
- {For enablement purposes only}
sheet 2
- MCU POWER
- HOST MCU INTERFACE
- Kinetis K82: 150MHz Cortex-M4 Secure MCU, 256KB Flash, 256KB SRAM, Full-Speed USB, 121-XFBGA
- i
- Layout Note:
  ==========
  Place Decaps as close as possible to the MCU PWR pads
- K82-CORTEX JTAG
- NET NAMES
- PIN FUNCTIONS USED
- STATUS LEDS
- KEY-PIN 7
- PIN FUNCTIONS USED
- NET NAMES
- i
- Layout Note:
  ==========
  XTAL as close as possible to MCU
- /SPI1_PCS1
- /SPI1_PCS0
- /SPI1_SCK
- /SPI1_SOUT
- /SPI1_SIN
- /FXIO0_D07
- /FXIO0_D08
- /FXIO0_D09
- /FXIO0_D10
- i
- Layout Note:
  ==========
  Place these 33 ohm resistors near the MCU.
- MCU RESET
sheet 3
- Revisions
- Rev
- Description
- Date
- Approved
- Table of Contents
- X1
- Initial Design
- 29 MAR 2023
- Jurgen Schroder
- 01
- Title
- A
- Release
- 15 MAY 2023
- Jurgen Schroder
- 02
- Block Diagram
- 1) Connect USB_5V_DC to U22 VREGIN
  2) Change net 3V3_BRD to net 3V3_VDD
  3) Change R87, R88 to J63
  4) Populate components to SWD header J28
  5) Populate R208 and R209
  6) Change U27 to NL27WZ14DFT2G from
     NL27WZ14MU1TCG (obsoleted)
  Release
- 03
- POWER
- B
- 25 SEPT 2023
- Jurgen Schroder
- 04
- NFCC Interface
- 05
- NFC Antenna
- 06
- IMX8 EVK
- 1) Change RB3 interface to iMX8 interface
  2) Change LED dim resistors
  3) Change R2 default setting to 3.3V
  4) Change J63 to solder jumper R7
  5) Add solder jumper R8 for GPIO3 options
  6) Add solder jumper R15, R16 for options
  Release
- 8 JUL 2024
- Jurgen Schroder
- 07
- K82
- C
- 08
- K20
- 1) Set R16 default short 1-2
  2) Add R15, R16 silkscreen
  3) Set J27 default short 1-2,3-4,5-6,7-8,
     11-12,13-14,15-16,17-18,19-20
  Release
- D
- 18 OCT 2024
- Jurgen Schroder
- PNEV7220BP2
  (DUAL HOST)
- REF DES
- JUMPER(DEFAULT)
- PAGE NAME
- J2,J4,J5
- 1-2
- 03 POWER
- J1,J3
- NONE
- 03 POWER
- J27
- 1-2,3-4,5-6,7-8,11-12,13-14,
  15-16,17-18,19-20
- 04 NFCC Interface
- J59,J60
- 1-2
- 08 K20
- J56
- NONE
- 08 K20
- REF DES
- ASSY_OPT
- PAGE NAME
- C5,C11,C24,C31,C66,R26
- DNP
- 03 POWER
- 1. Interrupted lines coded with the same letter or letter
      combinations are electrically connected.
- R90,R91
- DNP
- 04 NFCC Interface
- C92,C93,J29,J30,J31,J32,J33,
  R75,R81
- DNP
- 05 NFC Antenna
- 2. Device type number is for reference only. The number
      varies with the manufacturer.
- C87,C88,J58,J61,R195,R200,
  R203
- DNP
- 08 K20
- 3. Special signal usage:
- REF DES
- SHORT(DEFAULT)
- PAGE NAME
- _B Denotes - Active-Low Signal
- R2,R3
- 1-2
- 03 POWER
- <> or [] Denotes - Vectored Signals
- R7,R8,R16
- 1-2
- 04 NFCC Interface
- R15
- OPEN
- 04 NFCC Interface
- 4. Interpret diagram in accordance with American
  National Standards Institute specifications, current
  revision, with the exception of logic block symbology.
